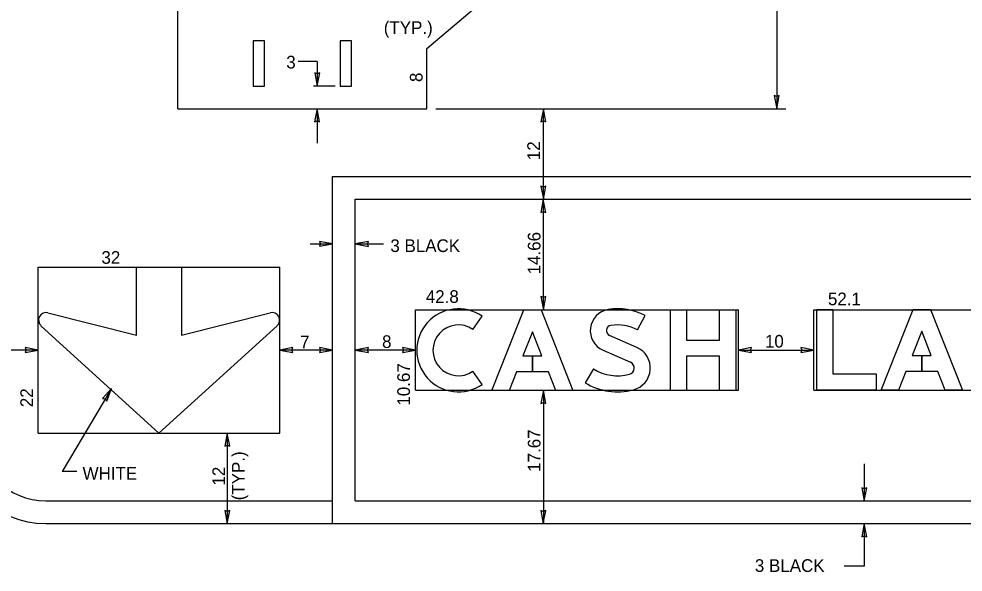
# Model space of a CAD drawing. Extents: x 319701 to 320014, y 1621790 to 1621996.
# Drawn here: x 319807.6 to 319911.9, y 1621816.2 to 1621877.3 of the extents above; entities that cross this region are included whole.
import ezdxf

# ---------------------------------------------------------------- set-up
doc = ezdxf.new("R2010")
doc.units = 0
for name, color, linetype in [('1', 7, 'Continuous'), ('40', 7, 'Continuous'), ('48', 7, 'Continuous'), ('52', 7, 'Continuous'), ('GSBWFill', 7, 'Continuous'), ('GSColorFill', 7, 'Continuous'), ('GSOutline', 7, 'Continuous'), ('SOILS_SP83_SHP', 7, 'Continuous')]:
    doc.layers.add(name, color=color, linetype=linetype)

msp = doc.modelspace()

# ---------------------------------------------------------------- linework, layer by layer
at = {"layer": '1'}
for p, q in [((319825.14, 1621867.37), (319825.14, 1621976.54)), ((319852.63, 1621874.04), (319887.63, 1621903.62)), ((319852.63, 1621867.37), (319852.63, 1621874.04)), ((319825.14, 1621867.37), (319852.63, 1621867.37)), ((319842.22, 1621821.54), (319842.22, 1621859.87)), ((319842.22, 1621859.87), (319980.55, 1621859.87)), ((319844.72, 1621857.37), (319978.05, 1621857.37)), ((319844.72, 1621824.04), (319844.72, 1621857.37)), ((319809.72, 1621831.54), (319809.72, 1621849.87)), ((319809.72, 1621849.87), (319836.39, 1621849.87)), ((319836.39, 1621831.54), (319836.39, 1621849.87)), ((319851.39, 1621836.27), (319851.39, 1621845.16)), ((319851.39, 1621845.16), (319887.05, 1621845.16)), ((319887.05, 1621836.27), (319887.05, 1621845.16)), ((319895.39, 1621845.16), (319938.8, 1621845.16)), ((319895.39, 1621836.27), (319895.39, 1621845.16)), ((319851.39, 1621836.27), (319887.05, 1621836.27)), ((319895.39, 1621836.27), (319938.8, 1621836.27)), ((319809.72, 1621831.54), (319836.39, 1621831.54)), ((319810.55, 1621824.04), (319842.22, 1621824.04)), ((319844.72, 1621824.04), (319970.55, 1621824.04)), ((319810.55, 1621821.54), (319970.55, 1621821.54))]:
    msp.add_line(p, q, dxfattribs=at)
for radius in [10, 7.5]:
    msp.add_arc((319810.55, 1621831.54), radius, 180, 270, dxfattribs=at)
at = {"layer": '40'}
for p, q in [((319834.72, 1621874.87), (319833.47, 1621874.87)), ((319833.47, 1621874.87), (319833.47, 1621869.87)), ((319834.72, 1621869.87), (319834.72, 1621874.87)), ((319844.3, 1621874.87), (319843.05, 1621874.87)), ((319843.05, 1621874.87), (319843.05, 1621869.87)), ((319844.3, 1621869.87), (319844.3, 1621874.87)), ((319833.47, 1621869.87), (319834.72, 1621869.87)), ((319843.05, 1621869.87), (319844.3, 1621869.87))]:
    msp.add_line(p, q, dxfattribs=at)
at = {"layer": '48'}
for p, q in [((319891.29, 1621911.96), (319891.29, 1621867.37)), ((319840.52, 1621872.59), (319838.44, 1621872.59)), ((319840.52, 1621872.59), (319840.52, 1621869.87)), ((319842.51, 1621869.87), (319840.11, 1621869.87)), ((319840.52, 1621867.38), (319840.52, 1621863.56)), ((319853.63, 1621867.37), (319892.29, 1621867.37)), ((319865.51, 1621857.37), (319865.51, 1621867.37)), ((319865.51, 1621845.16), (319865.51, 1621857.37)), ((319839.73, 1621852.44), (319842.22, 1621852.44)), ((319844.74, 1621852.44), (319847.86, 1621852.44)), ((319809.72, 1621840.71), (319800.55, 1621840.71)), ((319842.22, 1621840.71), (319836.39, 1621840.71)), ((319851.39, 1621840.71), (319844.72, 1621840.71)), ((319887.05, 1621840.71), (319895.39, 1621840.71)), ((319817.79, 1621836.47), (319812.36, 1621827.29)), ((319865.51, 1621836.27), (319865.51, 1621821.54)), ((319830.6, 1621821.54), (319830.6, 1621831.54)), ((319813.96, 1621827.29), (319812.36, 1621827.29)), ((319900.97, 1621824.04), (319900.97, 1621828.14)), ((319900.97, 1621816.88), (319900.97, 1621821.54)), ((319898.72, 1621816.88), (319900.97, 1621816.88))]:
    msp.add_line(p, q, dxfattribs=at)
at = {"layer": '52'}
for p, q in [((319840.52, 1621871.22), (319840.25, 1621871.33)), ((319840.25, 1621871.33), (319840.52, 1621869.88)), ((319840.52, 1621869.88), (319840.8, 1621871.33)), ((319840.8, 1621871.33), (319840.52, 1621871.22)), ((319891.28, 1621868.71), (319891.01, 1621868.82)), ((319891.01, 1621868.82), (319891.28, 1621867.37)), ((319891.28, 1621867.37), (319891.56, 1621868.82)), ((319891.56, 1621868.82), (319891.28, 1621868.71)), ((319840.52, 1621867.38), (319840.24, 1621865.93)), ((319840.79, 1621865.93), (319840.52, 1621867.38)), ((319865.51, 1621867.37), (319865.23, 1621865.92)), ((319865.78, 1621865.92), (319865.51, 1621867.37)), ((319840.24, 1621865.93), (319840.52, 1621866.04)), ((319840.52, 1621866.04), (319840.79, 1621865.93)), ((319865.23, 1621865.92), (319865.51, 1621866.03)), ((319865.51, 1621866.03), (319865.78, 1621865.92)), ((319865.51, 1621858.71), (319865.24, 1621858.82)), ((319865.24, 1621858.82), (319865.51, 1621857.37)), ((319865.51, 1621857.37), (319865.79, 1621858.82)), ((319865.79, 1621858.82), (319865.51, 1621858.71)), ((319865.5, 1621857.37), (319865.22, 1621855.92)), ((319865.77, 1621855.92), (319865.5, 1621857.37)), ((319865.22, 1621855.92), (319865.5, 1621856.03)), ((319865.5, 1621856.03), (319865.77, 1621855.92)), ((319842.23, 1621852.44), (319840.78, 1621852.72)), ((319840.78, 1621852.72), (319840.89, 1621852.44)), ((319840.89, 1621852.44), (319840.78, 1621852.17)), ((319840.78, 1621852.17), (319842.23, 1621852.44)), ((319846.18, 1621852.71), (319844.73, 1621852.44)), ((319844.73, 1621852.44), (319846.18, 1621852.16)), ((319846.07, 1621852.44), (319846.18, 1621852.71)), ((319846.18, 1621852.16), (319846.07, 1621852.44)), ((319865.51, 1621846.5), (319865.24, 1621846.61)), ((319865.24, 1621846.61), (319865.51, 1621845.16)), ((319865.51, 1621845.16), (319865.79, 1621846.61)), ((319865.79, 1621846.61), (319865.51, 1621846.5)), ((319809.71, 1621840.71), (319808.26, 1621840.99)), ((319808.26, 1621840.99), (319808.37, 1621840.71)), ((319837.84, 1621840.98), (319836.39, 1621840.71)), ((319836.39, 1621840.71), (319837.84, 1621840.43)), ((319837.73, 1621840.71), (319837.84, 1621840.98)), ((319837.84, 1621840.43), (319837.73, 1621840.71)), ((319842.23, 1621840.71), (319840.78, 1621840.99)), ((319840.78, 1621840.99), (319840.89, 1621840.71)), ((319846.18, 1621840.98), (319844.73, 1621840.71)), ((319846.07, 1621840.71), (319846.18, 1621840.98)), ((319851.39, 1621840.71), (319849.94, 1621840.99)), ((319849.94, 1621840.99), (319850.05, 1621840.71)), ((319850.05, 1621840.71), (319849.94, 1621840.44)), ((319849.94, 1621840.44), (319851.39, 1621840.71)), ((319888.5, 1621840.98), (319887.05, 1621840.71)), ((319887.05, 1621840.71), (319888.5, 1621840.43)), ((319888.39, 1621840.71), (319888.5, 1621840.98)), ((319888.5, 1621840.43), (319888.39, 1621840.71)), ((319895.39, 1621840.71), (319893.94, 1621840.99)), ((319893.94, 1621840.99), (319894.05, 1621840.71)), ((319894.05, 1621840.71), (319893.94, 1621840.44)), ((319893.94, 1621840.44), (319895.39, 1621840.71)), ((319808.37, 1621840.71), (319808.26, 1621840.44)), ((319808.26, 1621840.44), (319809.71, 1621840.71)), ((319840.89, 1621840.71), (319840.78, 1621840.44)), ((319840.78, 1621840.44), (319842.23, 1621840.71)), ((319844.73, 1621840.71), (319846.18, 1621840.43)), ((319846.18, 1621840.43), (319846.07, 1621840.71)), ((319817.79, 1621836.47), (319816.81, 1621835.36)), ((319817.29, 1621835.08), (319817.79, 1621836.47)), ((319865.51, 1621836.27), (319865.23, 1621834.82)), ((319865.78, 1621834.82), (319865.51, 1621836.27)), ((319816.81, 1621835.36), (319817.11, 1621835.31)), ((319817.11, 1621835.31), (319817.29, 1621835.08)), ((319865.23, 1621834.82), (319865.51, 1621834.93)), ((319865.51, 1621834.93), (319865.78, 1621834.82)), ((319830.59, 1621831.54), (319830.31, 1621830.09)), ((319830.86, 1621830.09), (319830.59, 1621831.54)), ((319830.31, 1621830.09), (319830.59, 1621830.2)), ((319830.59, 1621830.2), (319830.86, 1621830.09)), ((319900.96, 1621825.38), (319900.69, 1621825.49)), ((319900.69, 1621825.49), (319900.96, 1621824.04)), ((319900.96, 1621824.04), (319901.24, 1621825.49)), ((319901.24, 1621825.49), (319900.96, 1621825.38)), ((319830.59, 1621822.88), (319830.32, 1621822.99)), ((319830.32, 1621822.99), (319830.59, 1621821.54)), ((319830.59, 1621821.54), (319830.87, 1621822.99)), ((319830.87, 1621822.99), (319830.59, 1621822.88)), ((319865.5, 1621822.88), (319865.23, 1621822.99)), ((319865.23, 1621822.99), (319865.5, 1621821.54)), ((319865.5, 1621821.54), (319865.78, 1621822.99)), ((319865.78, 1621822.99), (319865.5, 1621822.88)), ((319900.96, 1621821.54), (319900.68, 1621820.09)), ((319901.23, 1621820.09), (319900.96, 1621821.54)), ((319900.68, 1621820.09), (319900.96, 1621820.2)), ((319900.96, 1621820.2), (319901.23, 1621820.09))]:
    msp.add_line(p, q, dxfattribs=at)
at = {"layer": 'GSBWFill'}
for p, q in [((319857.72, 1621842.99), (319858.74, 1621844.45)), ((319875.9, 1621842.94), (319876.74, 1621844.51)), ((319875.83, 1621841.01), (319872.82, 1621842.33)), ((319872.11, 1621840.7), (319875.12, 1621839.38)), ((319871.04, 1621838.62), (319870.12, 1621837.1)), ((319858.74, 1621836.92), (319857.72, 1621838.38)), ((319857.72, 1621838.38), (319857.72, 1621838.38))]:
    msp.add_line(p, q, dxfattribs=at)
for points in [[(319864.29, 1621840.07), (319864.29, 1621838.3), (319862.53, 1621838.3), (319861.72, 1621836.25), (319859.8, 1621836.25), (319863.34, 1621845.14), (319865.25, 1621845.14), (319868.78, 1621836.25), (319866.87, 1621836.25), (319866.06, 1621838.3), (319864.29, 1621838.3), (319864.29, 1621840.07), (319865.35, 1621840.07), (319864.29, 1621842.73), (319863.24, 1621840.07)], [(319886.75, 1621836.25), (319884.97, 1621836.25), (319884.97, 1621840.02), (319881.32, 1621840.02), (319881.32, 1621836.25), (319879.54, 1621836.25), (319879.54, 1621845.14), (319881.32, 1621845.14), (319881.32, 1621841.8), (319884.97, 1621841.8), (319884.97, 1621845.14), (319886.75, 1621845.14)], [(319897.48, 1621838.07), (319902.28, 1621838.07), (319902.28, 1621836.29), (319895.7, 1621836.29), (319895.7, 1621845.19), (319897.48, 1621845.19)], [(319907.3, 1621840.12), (319907.3, 1621838.34), (319905.54, 1621838.34), (319904.73, 1621836.29), (319902.81, 1621836.29), (319906.35, 1621845.19), (319908.26, 1621845.19), (319911.79, 1621836.29), (319909.88, 1621836.29), (319909.07, 1621838.34), (319907.3, 1621838.34), (319907.3, 1621840.12), (319908.36, 1621840.12), (319907.3, 1621842.78), (319906.25, 1621840.12)]]:
    msp.add_lwpolyline(points, close=True, dxfattribs=at)
for radius in [4.59, 2.81]:
    msp.add_arc((319856.12, 1621840.68), radius, 55.2129, 304.7871, dxfattribs=at)
for centre, major_axis, start_param, end_param in [((319873.05, 1621842.86), (0, 2.36), 0.165591, 2.728374), ((319873.72, 1621838.87), (0, 6.4), 5.791375, 6.448776), ((319873.05, 1621842.86), (0, 0.578), 0.165591, 2.728374), ((319873.72, 1621838.87), (0, 4.62), 5.791375, 6.448776), ((319874.83, 1621838.73), (0, 2.49), 3.394273, 5.869966), ((319873.72, 1621843.03), (0, 5.16), 2.595642, 3.394273), ((319874.83, 1621838.73), (0, 0.711), 3.394273, 5.869966), ((319873.72, 1621843.03), (0, 6.94), 2.595642, 3.394273)]:
    msp.add_ellipse(centre, major_axis=major_axis, ratio=0.999996, start_param=start_param, end_param=end_param, dxfattribs=at)
at = {"layer": 'GSColorFill'}
for p, q in [((319857.72, 1621842.99), (319858.74, 1621844.45)), ((319875.9, 1621842.94), (319876.74, 1621844.51)), ((319875.83, 1621841.01), (319872.82, 1621842.33)), ((319872.11, 1621840.7), (319875.12, 1621839.38)), ((319871.04, 1621838.62), (319870.12, 1621837.1)), ((319858.74, 1621836.92), (319857.72, 1621838.38)), ((319857.72, 1621838.38), (319857.72, 1621838.38))]:
    msp.add_line(p, q, dxfattribs=at)
for points in [[(319864.29, 1621840.07), (319864.29, 1621838.3), (319862.53, 1621838.3), (319861.72, 1621836.25), (319859.8, 1621836.25), (319863.34, 1621845.14), (319865.25, 1621845.14), (319868.78, 1621836.25), (319866.87, 1621836.25), (319866.06, 1621838.3), (319864.29, 1621838.3), (319864.29, 1621840.07), (319865.35, 1621840.07), (319864.29, 1621842.73), (319863.24, 1621840.07)], [(319886.75, 1621836.25), (319884.97, 1621836.25), (319884.97, 1621840.02), (319881.32, 1621840.02), (319881.32, 1621836.25), (319879.54, 1621836.25), (319879.54, 1621845.14), (319881.32, 1621845.14), (319881.32, 1621841.8), (319884.97, 1621841.8), (319884.97, 1621845.14), (319886.75, 1621845.14)], [(319897.48, 1621838.07), (319902.28, 1621838.07), (319902.28, 1621836.29), (319895.7, 1621836.29), (319895.7, 1621845.19), (319897.48, 1621845.19)], [(319907.3, 1621840.12), (319907.3, 1621838.34), (319905.54, 1621838.34), (319904.73, 1621836.29), (319902.81, 1621836.29), (319906.35, 1621845.19), (319908.26, 1621845.19), (319911.79, 1621836.29), (319909.88, 1621836.29), (319909.07, 1621838.34), (319907.3, 1621838.34), (319907.3, 1621840.12), (319908.36, 1621840.12), (319907.3, 1621842.78), (319906.25, 1621840.12)]]:
    msp.add_lwpolyline(points, close=True, dxfattribs=at)
for radius in [4.59, 2.81]:
    msp.add_arc((319856.12, 1621840.68), radius, 55.2129, 304.7871, dxfattribs=at)
for centre, major_axis, start_param, end_param in [((319873.05, 1621842.86), (0, 2.36), 0.165591, 2.728374), ((319873.72, 1621838.87), (0, 6.4), 5.791375, 6.448776), ((319873.05, 1621842.86), (0, 0.578), 0.165591, 2.728374), ((319873.72, 1621838.87), (0, 4.62), 5.791375, 6.448776), ((319874.83, 1621838.73), (0, 2.49), 3.394273, 5.869966), ((319873.72, 1621843.03), (0, 5.16), 2.595642, 3.394273), ((319874.83, 1621838.73), (0, 0.711), 3.394273, 5.869966), ((319873.72, 1621843.03), (0, 6.94), 2.595642, 3.394273)]:
    msp.add_ellipse(centre, major_axis=major_axis, ratio=0.999996, start_param=start_param, end_param=end_param, dxfattribs=at)
at = {"layer": 'GSOutline'}
for p, q in [((319857.72, 1621842.99), (319858.74, 1621844.45)), ((319875.9, 1621842.94), (319876.74, 1621844.51)), ((319875.83, 1621841.01), (319872.82, 1621842.33)), ((319872.11, 1621840.7), (319875.12, 1621839.38)), ((319871.04, 1621838.62), (319870.12, 1621837.1)), ((319858.74, 1621836.92), (319857.72, 1621838.38)), ((319857.72, 1621838.38), (319857.72, 1621838.38))]:
    msp.add_line(p, q, dxfattribs=at)
for points in [[(319866.06, 1621838.3), (319862.53, 1621838.3), (319861.72, 1621836.25), (319859.8, 1621836.25), (319863.34, 1621845.14), (319865.25, 1621845.14), (319868.78, 1621836.25), (319866.87, 1621836.25)], [(319886.75, 1621836.25), (319884.97, 1621836.25), (319884.97, 1621840.02), (319881.32, 1621840.02), (319881.32, 1621836.25), (319879.54, 1621836.25), (319879.54, 1621845.14), (319881.32, 1621845.14), (319881.32, 1621841.8), (319884.97, 1621841.8), (319884.97, 1621845.14), (319886.75, 1621845.14)], [(319897.48, 1621838.07), (319902.28, 1621838.07), (319902.28, 1621836.29), (319895.7, 1621836.29), (319895.7, 1621845.19), (319897.48, 1621845.19)], [(319909.07, 1621838.34), (319905.54, 1621838.34), (319904.73, 1621836.29), (319902.81, 1621836.29), (319906.35, 1621845.19), (319908.26, 1621845.19), (319911.79, 1621836.29), (319909.88, 1621836.29)], [(319863.24, 1621840.07), (319865.35, 1621840.07), (319864.29, 1621842.73)], [(319906.25, 1621840.12), (319908.36, 1621840.12), (319907.3, 1621842.78)]]:
    msp.add_lwpolyline(points, close=True, dxfattribs=at)
for radius in [4.59, 2.81]:
    msp.add_arc((319856.12, 1621840.68), radius, 55.2129, 304.7871, dxfattribs=at)
for centre, major_axis, start_param, end_param in [((319873.05, 1621842.86), (0, 2.36), 0.165591, 2.728374), ((319873.72, 1621838.87), (0, 6.4), 5.791375, 6.448776), ((319873.05, 1621842.86), (0, 0.578), 0.165591, 2.728374), ((319873.72, 1621838.87), (0, 4.62), 5.791375, 6.448776), ((319874.83, 1621838.73), (0, 2.49), 3.394273, 5.869966), ((319873.72, 1621843.03), (0, 5.16), 2.595642, 3.394273), ((319874.83, 1621838.73), (0, 0.711), 3.394273, 5.869966), ((319873.72, 1621843.03), (0, 6.94), 2.595642, 3.394273)]:
    msp.add_ellipse(centre, major_axis=major_axis, ratio=0.999996, start_param=start_param, end_param=end_param, dxfattribs=at)
at = {"layer": 'SOILS_SP83_SHP'}
for p, q in [((319820.55, 1621842.35), (319820.55, 1621849.85)), ((319820.55, 1621849.85), (319825.54, 1621849.85)), ((319825.54, 1621849.85), (319825.54, 1621842.35)), ((319810.76, 1621844.83), (319820.55, 1621842.35)), ((319825.54, 1621842.35), (319835.33, 1621844.83)), ((319823.04, 1621831.54), (319810.01, 1621843.4)), ((319836.09, 1621843.4), (319823.04, 1621831.54))]:
    msp.add_line(p, q, dxfattribs=at)
for centre, start, end in [((319810.58, 1621844.02), 75.8248, 227.7118), ((319835.54, 1621844.02), 312.2846, 104.1718)]:
    msp.add_arc(centre, 0.832, start, end, dxfattribs=at)

# ---------------------------------------------------------------- texts
at = {"layer": '48'}
for s, p in [('(TYP.)', (319847.88, 1621875.63)), ('3', (319837.11, 1621871.82)), ('3 BLACK', (319848.61, 1621851.54)), ('32', (319816.69, 1621850.24)), ('42.8', (319852.52, 1621845.92)), ('52.1', (319896.94, 1621845.66)), ('7', (319838.63, 1621840.89)), ('8', (319847.69, 1621840.94)), ('10', (319889.98, 1621840.98)), ('WHITE', (319814.61, 1621826.38)), ('3 BLACK', (319888.87, 1621816.2))]:
    msp.add_text(s, height=1.4, dxfattribs=at).set_placement(p)
for s, p in [('8', (319852.16, 1621870.32)), ('12', (319865.13, 1621861.69)), ('14.66', (319865.19, 1621849.07)), ('10.67', (319850.77, 1621834.57)), ('22', (319809.13, 1621834.4)), ('17.67', (319865.19, 1621827.26)), ('(TYP.)', (319832.5, 1621824.11)), ('12', (319830.35, 1621825.74))]:
    msp.add_text(s, height=1.4, rotation=90, dxfattribs=at).set_placement(p)

doc.saveas('drawing.dxf')
